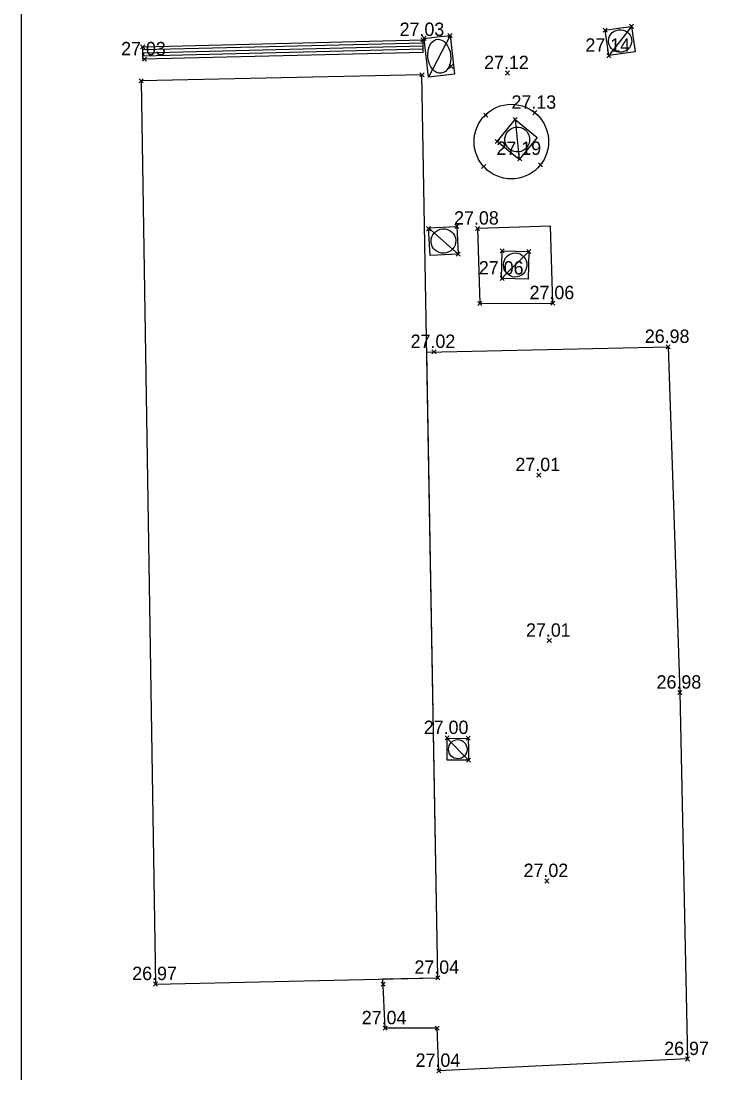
# Model space of a CAD drawing. Extents: x 37864 to 38032, y 453991 to 454052.
# Drawn here: x 37864.06 to 37879.07, y 454016.08 to 454038.52 of the extents above; entities that cross this region are included whole.
import ezdxf

# ---------------------------------------------------------------- set-up
doc = ezdxf.new("R2010")
doc.units = 0
for name, color, linetype in [('DH_CALCUL SURFACE-TEXTE', 7, 'Continuous'), ('DH_TEXTE', 7, 'Continuous'), ('GO MUR EXTERIEUR', 7, 'Continuous'), ('GO_POTEAU', 7, 'Continuous'), ('PS_Mid', 7, 'Continuous'), ('PS_Solid', 7, 'Continuous'), ('SO_MENUISERIE EXT DOR', 7, 'Continuous')]:
    doc.layers.add(name, color=color, linetype=linetype)

# ---------------------------------------------------------------- blocks, each defined once
blk = doc.blocks.new('A-REGARD')
for p, q in [((0, 1), (1, 1)), ((0, 0), (1, 1)), ((0, 0), (0, 1)), ((1, 1), (1, 0)), ((0.5, 0), (0, 0)), ((1, 0), (0.5, 0))]:
    blk.add_line(p, q)
blk.add_circle((0.5, 0.5), 0.438)
blk = doc.blocks.new('A-GRIL')
for p, q in [((0, 1), (1, 1)), ((0, 1), (0, 0.75)), ((1, 1), (1, 0.75)), ((0, 0.75), (0, 0.5)), ((0, 0.75), (1, 0.75)), ((1, 0.75), (1, 0.5)), ((0, 0.5), (0, 0.25)), ((0, 0.5), (1, 0.5)), ((1, 0.5), (1, 0.25)), ((0, 0.25), (0, 0)), ((0, 0.25), (1, 0.25)), ((1, 0.25), (1, 0)), ((1, 0), (0, 0))]:
    blk.add_line(p, q)
blk = doc.blocks.new('POINT_DISPLAY')
for p, q in [((-0.04375, -0.04375), (0.04375, 0.04375)), ((-0.04375, 0.04375), (0.04375, -0.04375))]:
    blk.add_line(p, q)
blk = doc.blocks.new('POINTCOT')
blk.add_blockref('POINT_DISPLAY', (0, 0))

msp = doc.modelspace()

# ---------------------------------------------------------------- linework, layer by layer
at = {"layer": 'DEFPOINTS'}
msp.add_lwpolyline([(37864.064, 453990.816), (37946.064, 453990.816), (37946.064, 454048.216), (37864.064, 454048.216)], close=True, dxfattribs=at)
at = {"layer": 'GO MUR EXTERIEUR'}
msp.add_lwpolyline([(37866.936, 454017.981), (37872.96, 454018.115), (37872.623, 454037.373), (37866.629, 454037.241)], close=True, dxfattribs=at)
at = {"layer": 'PS_Mid'}
for points in [[(37873.807, 454034.093), (37873.858, 454032.494), (37875.418, 454032.502), (37875.366, 454034.143), (37873.807, 454034.093)], [(37871.791, 454018.089), (37872.96, 454018.115), (37872.726, 454031.459), (37877.878, 454031.57), (37878.129, 454024.196), (37878.293, 454016.382), (37872.985, 454016.131), (37872.949, 454017.038), (37871.836, 454017.039), (37871.791, 454018.089)]]:
    msp.add_lwpolyline(points, dxfattribs=at)
msp.add_circle((37874.531, 454035.947), 0.795, dxfattribs=at)
at = {"layer": 'PS_Solid'}
msp.add_lwpolyline([(37866.936, 454017.981), (37872.96, 454018.115), (37872.623, 454037.373), (37866.629, 454037.241)], dxfattribs=at)

# ---------------------------------------------------------------- block references
at = {"layer": 'DH_CALCUL SURFACE-TEXTE', "rotation": 2.2526485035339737e-05}
for p in [(37877.094, 454038.405), (37872.668, 454038.149), (37873.222, 454038.212), (37876.533, 454038.325), (37866.66, 454037.967), (37872.644, 454038.116), (37866.699, 454037.704), (37876.61, 454037.78), (37873.247, 454037.553), (37866.629, 454037.241), (37872.623, 454037.373), (37874.447, 454037.409), (37875.032, 454036.564), (37873.985, 454036.512), (37874.615, 454036.418), (37874.231, 454035.95), (37874.711, 454035.58), (37875.152, 454035.451), (37873.941, 454035.415), (37872.765, 454034.09), (37873.365, 454034.139), (37873.807, 454034.093), (37873.398, 454033.548), (37874.335, 454033.617), (37874.905, 454033.603), (37874.335, 454033.03), (37873.858, 454032.494), (37875.418, 454032.502), (37872.879, 454031.462), (37877.878, 454031.57), (37875.116, 454028.835), (37875.342, 454025.305), (37878.129, 454024.196), (37873.159, 454023.229), (37873.611, 454023.225), (37873.616, 454022.757), (37875.29, 454020.179), (37866.936, 454017.981), (37871.796, 454017.98), (37872.96, 454018.115), (37871.836, 454017.039), (37872.949, 454017.038), (37878.293, 454016.382), (37872.985, 454016.131)]:
    msp.add_blockref('POINTCOT', p, dxfattribs=at)
at = {"layer": 'DH_TEXTE'}
for p, xscale, yscale, rotation in [((37874.615, 454036.418), 0.6054364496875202, 0.6060132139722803, -129.34230381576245), ((37874.905, 454033.603), 0.5701535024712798, 0.5871244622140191, 178.66057200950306), ((37873.616, 454022.757), 0.46789552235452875, 0.451478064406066, 90.67418991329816)]:
    msp.add_blockref('A-REGARD', p, dxfattribs=dict(at, xscale=xscale, yscale=yscale, rotation=rotation))
at = {"layer": 'SO_MENUISERIE EXT DOR'}
for name, p, xscale, yscale, rotation in [('A-REGARD', (37877.094, 454038.405), 0.5669079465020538, 0.5505522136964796, -171.88689627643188), ('A-REGARD', (37873.222, 454038.212), 0.5576843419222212, 0.8307691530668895, -173.43745525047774), ('A-GRIL', (37872.644, 454038.116), 5.986300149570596, 0.266026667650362, -178.57759171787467), ('A-REGARD', (37873.398, 454033.548), 0.5916208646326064, 0.6026969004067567, 93.16261782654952)]:
    msp.add_blockref(name, p, dxfattribs=dict(at, xscale=xscale, yscale=yscale, rotation=rotation))

# ---------------------------------------------------------------- texts
at = {"layer": 'GO_POTEAU'}
for s, p in [('27.03', (37872.146, 454038.2)), ('27.03', (37866.201, 454037.788)), ('27.14', (37876.112, 454037.864)), ('27.12', (37873.949, 454037.493)), ('27.13', (37874.534, 454036.648)), ('27.19', (37874.213, 454035.664)), ('27.08', (37873.309, 454034.177)), ('27.06', (37873.837, 454033.113)), ('27.06', (37874.92, 454032.586)), ('26.98', (37877.38, 454031.654)), ('27.02', (37872.381, 454031.546)), ('27.01', (37874.618, 454028.919)), ('27.01', (37874.844, 454025.388)), ('26.98', (37877.631, 454024.28)), ('27.00', (37872.661, 454023.313)), ('27.02', (37874.792, 454020.263)), ('27.04', (37872.462, 454018.199)), ('26.97', (37866.438, 454018.065)), ('27.04', (37871.338, 454017.123)), ('26.97', (37877.795, 454016.466)), ('27.04', (37872.487, 454016.214))]:
    msp.add_text(s, height=0.285, rotation=0, dxfattribs=at).set_placement(p)

doc.saveas('drawing.dxf')
